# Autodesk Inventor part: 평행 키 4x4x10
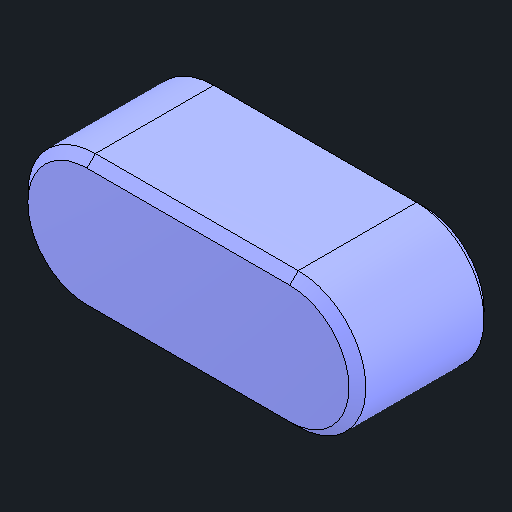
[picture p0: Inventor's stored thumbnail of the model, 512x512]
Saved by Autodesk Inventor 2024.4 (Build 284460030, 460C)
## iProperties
Created: 2026-08
Part Number: 평행 키 4x4x10
Material: 강철, 연강
Description: 키 및 해당 키홈
Document SubType Name: Modeling
Designer: user
Density: 7.85 g/cm^3
Appearance: 기본값
Author: jhkim
Sending System: Autodesk Inventor 2027
Preprocessor: ST-DEVELOPER v20.1
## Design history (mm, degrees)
feature "Solid1"
node "솔리드1"
